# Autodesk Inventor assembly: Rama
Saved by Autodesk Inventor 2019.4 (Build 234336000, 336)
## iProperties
Created: 2020-01
Part Number: Rama
Document SubType Name: Assembly
Designer: Administrator
Title: Rama v7
Author: Administrator
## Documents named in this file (2)
- c:\worker\convert-fusion-r01\tmp\job-1\36\output\files\9be13dbb-4289-4c70-bb27-03d32c1206a2\Rama v7.iam
- c:\worker\convert-fusion-r01\tmp\job-1\36\output\files\9be13dbb-4289-4c70-bb27-03d32c1206a2\Rama v7.ipt
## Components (1 placed, 1 different names)
1. Rama v7
